// Mitsubishi GX Works2 project: MC-20MR-4MTS-F430-H3U-B   PLC: FX3G

PROGRAM MAIN
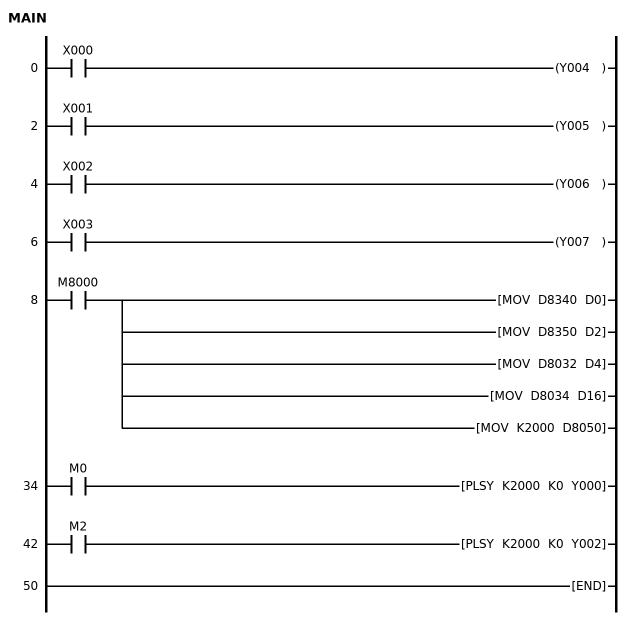
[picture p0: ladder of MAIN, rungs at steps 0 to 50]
0     LD      X000
      OUT     Y004
2     LD      X001
      OUT     Y005
4     LD      X002
      OUT     Y006
6     LD      X003
      OUT     Y007
8     LD      M8000
      MOV     D8340 D0
      MOV     D8350 D2
      MOV     D8032 D4
      MOV     D8034 D16
      MOV     K2000 D8050
34    LD      M0
      PLSY    K2000 K0 Y000
42    LD      M2
      PLSY    K2000 K0 Y002
50    END
END_PROGRAM
